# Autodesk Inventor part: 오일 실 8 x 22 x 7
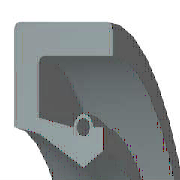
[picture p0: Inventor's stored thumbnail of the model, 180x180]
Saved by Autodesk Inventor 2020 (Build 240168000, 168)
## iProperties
Created: 2012-02
Part Number: 오일 실 8 x 22 x 7
Material: 고무
Description: 오일-실
Document SubType Name: Modeling
Standard: KS B 2804
Designer: test
Standards Organization: KS
Language: ko-KR
Size Designation: S - 8 22 7
Categories: <MemberInstance><Categories><Category DisplayName="샤프트 부품" InternalName="7f7aeb1f-a693-4053-b835-cee3144e0d98" Mnemonic="SHFT"><Category DisplayName="실링" Intern
Density: 0.93 g/cm^3
Appearance: 고무 - 검은색 - 버전 1.1
IsCustomPart: 1
Author: test
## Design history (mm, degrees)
revolve "본체" stored, may be unused: angle "d17" = 90 deg
revolve "스프링1" stored, may be unused: angle "d18" = 90 deg
body "Solid1"
sketch "스케치1"
  geometry: L1 (0, 11)-(7, 11); L2 (7, 11)-(7, 9.75); L3 (7, 9.75)-(1.75, 9.75); L4 (0, 11)-(0, 6.1); L5 (0, 6.1)-(1.75, 5.75); L6 (1.75, 5.75)-(4.9, 4); L7 (4.9, 4)-(0, 4); L8 (6.3, 4.875)-(6.3, 6.1); L9 (0, 0)-(9.586, 0) reference; L10 (4.9, 4)-(6.3, 4.875); L11 (0, 18)-(0, -3) reference; L12 (-1.917, 0)-(11.503, 0) reference; L13 (4.2, 6.1)-(1.75, 6.59); L14 (1.75, 6.59)-(1.75, 9.75); L15 (6.3, 6.1)-(5.6, 6.1); C1 r 0.455 at (4.9, 6.1); A1 r 0.7 centre (4.9, 6.1) between (5.6, 6.1) and (4.2, 6.1)
  constraints: 26 end point, 5 horizontal alignment, 4 perpendicular, 2 centre point, 2 collinear, 2 horizontal, 2 parallel, 2 point on circle, 2 point on line, 2 vertical alignment, 1 coincident
  dimensions: "d0" = 22 diameter of L1 L9 (= SD2); "d1" = 9.75 diameter of L8.start L9 (= ABDM); "d2" = 1.25 distance of L1.end L2.end (computed from SD); "d3" = 0.91 diameter of C1 (= SPDI); "d4" = 1.4 diameter of A1 (= SPDA); "d5" = 8 diameter of L6.end L9 (= NND); "d6" = 11.5 diameter of L5.end L9 (= TKDM); "d7" = 12.2 diameter of L4.end L9 (= HLDM); "d8" = 4.9 distance from line of C1.centre L4 (= SPDST); "d9" = 6.3 distance between parallel lines of L8 L4 (= SDI); "d10" = 7 distance between parallel lines of L2 L4 (= SWDT); "d12" = 1.75 distance between parallel lines of L14 L4 (= SD)
fillet "모깎기1" dims "d11" = 0.3 (= RR)
other parameters: "SD2" = 22 [user parameter; used in 1 equation term], "SWDT" = 7 [user parameter; used in 1 equation term], "RR" = 0.3 [user parameter; used in 1 equation term], "SD" = 1.75 [user parameter; used in 2 equation terms], "NND" = 8 [user parameter; used in 1 equation term], "SPDA" = 1.4 [user parameter; used in 1 equation term], "SPDI" = 0.91 [user parameter; used in 1 equation term], "TKDM" = 11.5 [user parameter; used in 1 equation term], "HLDM" = 12.2 [user parameter; used in 1 equation term], "ABDM" = 9.75 [user parameter; used in 1 equation term], "SDI" = 6.3 [user parameter; used in 1 equation term], "SPDST" = 4.9 [user parameter; used in 1 equation term], "d13" = 0, "d14" = 0, "d15" = 0, "LAB" = 0.35 [user parameter]
